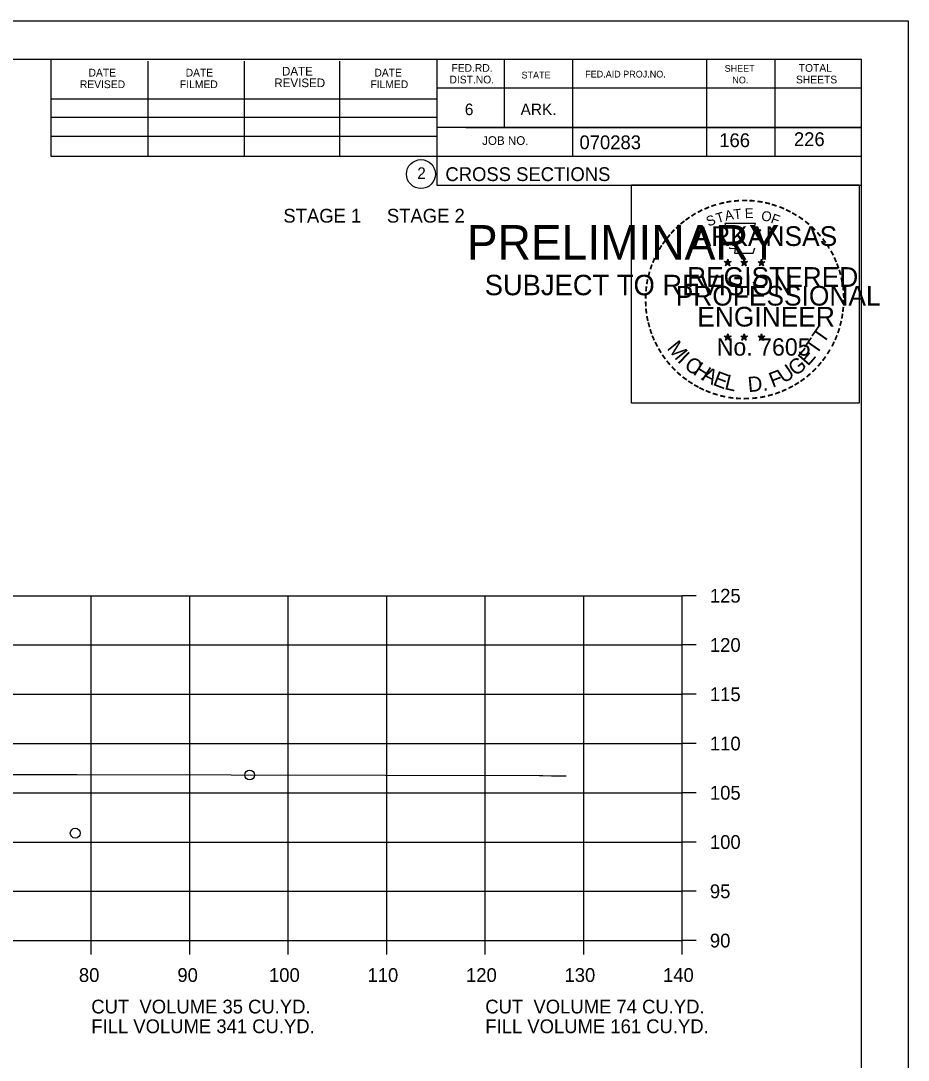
# Model space of a CAD drawing. Extents: x 1175611 to 1176402, y -433344 to -416213.
# Drawn here: x 1175853.8 to 1175943.9, y -429182.3 to -429076.8 of the extents above; entities that cross this region are included whole.
import ezdxf

# ---------------------------------------------------------------- set-up
doc = ezdxf.new("R2010")
doc.units = 0
for name, color, linetype in [('Default', 7, 'Continuous'), ('R_Axis', 7, 'Continuous'), ('R_Axis Annot', 7, 'Continuous'), ('R_Border', 7, 'Continuous'), ('R_Border Notes', 7, 'Continuous'), ('R_Border PE', 7, 'Continuous'), ('R_Border Prem', 7, 'Continuous'), ('R_Exist Surface', 7, 'Continuous'), ('R_Grid', 7, 'Continuous'), ('R_No Plot', 7, 'Continuous')]:
    doc.layers.add(name, color=color, linetype=linetype)

msp = doc.modelspace()

# ---------------------------------------------------------------- linework, layer by layer
at = {"layer": 'R_Axis'}
for p, q in [((1175920.97, -429170.13), (1175920.97, -429135.13)), ((1175922.37, -429135.13), (1175920.97, -429135.13)), ((1175922.37, -429140.13), (1175920.97, -429140.13)), ((1175922.37, -429145.13), (1175920.97, -429145.13)), ((1175922.37, -429150.13), (1175920.97, -429150.13)), ((1175922.37, -429155.13), (1175920.97, -429155.13)), ((1175922.37, -429160.13), (1175920.97, -429160.13)), ((1175922.37, -429165.13), (1175920.97, -429165.13)), ((1175640.97, -429170.13), (1175920.97, -429170.13)), ((1175860.97, -429171.53), (1175860.97, -429170.13)), ((1175870.97, -429171.53), (1175870.97, -429170.13)), ((1175880.97, -429171.53), (1175880.97, -429170.13)), ((1175890.97, -429171.53), (1175890.97, -429170.13)), ((1175900.97, -429171.53), (1175900.97, -429170.13)), ((1175910.97, -429171.53), (1175910.97, -429170.13)), ((1175920.97, -429171.53), (1175920.97, -429170.13)), ((1175922.37, -429170.13), (1175920.97, -429170.13))]:
    msp.add_line(p, q, dxfattribs=at)
at = {"layer": 'R_Border'}
for p, q in [((1175622.97, -429080.67), (1175939.15, -429080.67)), ((1175856.89, -429090.55), (1175856.89, -429080.67)), ((1175896.05, -429080.67), (1175896.05, -429093.47)), ((1175902.89, -429080.67), (1175902.89, -429087.61)), ((1175909.83, -429080.67), (1175909.83, -429090.55)), ((1175923.41, -429080.67), (1175923.41, -429090.55)), ((1175930.35, -429080.67), (1175930.35, -429090.55)), ((1175939.15, -429286.13), (1175939.15, -429080.67)), ((1175866.75, -429090.55), (1175866.75, -429080.87)), ((1175876.51, -429090.55), (1175876.51, -429080.87)), ((1175886.19, -429090.55), (1175886.19, -429080.87)), ((1175939.15, -429083.61), (1175896.05, -429083.61)), ((1175939.15, -429083.59), (1175939.15, -429083.59)), ((1175856.89, -429084.69), (1175896.05, -429084.69)), ((1175856.89, -429086.55), (1175896.05, -429086.55)), ((1175939.15, -429087.61), (1175896.05, -429087.61)), ((1175899.01, -429087.61), (1175939.15, -429087.61)), ((1175856.89, -429090.55), (1175856.89, -429088.49)), ((1175856.89, -429088.49), (1175896.05, -429088.49)), ((1175939.15, -429090.55), (1175856.89, -429090.55)), ((1175896.05, -429093.47), (1175939.15, -429093.47))]:
    msp.add_line(p, q, dxfattribs=at)
msp.add_circle((1175894.44, -429092.33), 1.47, dxfattribs=at)
at = {"layer": 'R_Border PE'}
for p, q in [((1175925.23, -429101.22), (1175925.58, -429101.33)), ((1175925.23, -429101.22), (1175925.49, -429101.27)), ((1175925.23, -429101.22), (1175925.47, -429101.34)), ((1175925.37, -429101.63), (1175925.58, -429101.33)), ((1175925.37, -429101.63), (1175925.49, -429101.39)), ((1175925.37, -429101.63), (1175925.58, -429101.41)), ((1175925.58, -429100.97), (1175925.54, -429101.22)), ((1175925.58, -429101.33), (1175925.58, -429100.97)), ((1175925.58, -429100.97), (1175925.63, -429101.22)), ((1175925.93, -429101.22), (1175925.58, -429101.33)), ((1175925.8, -429101.63), (1175925.58, -429101.33)), ((1175925.8, -429101.63), (1175925.58, -429101.42)), ((1175925.93, -429101.22), (1175925.64, -429101.27)), ((1175925.8, -429101.63), (1175925.66, -429101.34)), ((1175925.93, -429101.22), (1175925.73, -429101.32)), ((1175926.9, -429101.22), (1175927.25, -429101.33)), ((1175926.9, -429101.22), (1175927.16, -429101.27)), ((1175926.9, -429101.22), (1175927.14, -429101.34)), ((1175927.04, -429101.63), (1175927.25, -429101.33)), ((1175927.04, -429101.63), (1175927.16, -429101.39)), ((1175927.04, -429101.63), (1175927.25, -429101.41)), ((1175927.25, -429100.97), (1175927.21, -429101.22)), ((1175927.25, -429101.33), (1175927.25, -429100.97)), ((1175927.25, -429100.97), (1175927.3, -429101.22)), ((1175927.6, -429101.22), (1175927.25, -429101.33)), ((1175927.47, -429101.63), (1175927.25, -429101.33)), ((1175927.47, -429101.63), (1175927.25, -429101.42)), ((1175927.6, -429101.22), (1175927.31, -429101.27)), ((1175927.47, -429101.63), (1175927.33, -429101.34)), ((1175927.6, -429101.22), (1175927.4, -429101.32)), ((1175928.67, -429101.23), (1175929.02, -429101.34)), ((1175928.67, -429101.23), (1175928.92, -429101.28)), ((1175928.67, -429101.23), (1175928.91, -429101.36)), ((1175928.8, -429101.64), (1175929.02, -429101.34)), ((1175928.8, -429101.64), (1175928.93, -429101.4)), ((1175928.8, -429101.64), (1175929.02, -429101.42)), ((1175929.02, -429100.98), (1175928.98, -429101.23)), ((1175929.02, -429101.34), (1175929.02, -429100.98)), ((1175929.02, -429100.98), (1175929.07, -429101.23)), ((1175929.36, -429101.23), (1175929.02, -429101.34)), ((1175929.23, -429101.64), (1175929.02, -429101.34)), ((1175929.23, -429101.64), (1175929.02, -429101.43)), ((1175929.36, -429101.23), (1175929.08, -429101.28)), ((1175929.23, -429101.64), (1175929.09, -429101.35)), ((1175929.36, -429101.23), (1175929.16, -429101.34)), ((1175925.23, -429108.79), (1175925.58, -429108.91)), ((1175925.23, -429108.79), (1175925.48, -429108.84)), ((1175925.23, -429108.79), (1175925.47, -429108.92)), ((1175925.36, -429109.2), (1175925.58, -429108.91)), ((1175925.36, -429109.2), (1175925.49, -429108.96)), ((1175925.36, -429109.2), (1175925.58, -429108.99)), ((1175925.58, -429108.54), (1175925.54, -429108.79)), ((1175925.58, -429108.91), (1175925.58, -429108.54)), ((1175925.58, -429108.54), (1175925.63, -429108.79)), ((1175925.93, -429108.79), (1175925.58, -429108.91)), ((1175925.79, -429109.2), (1175925.58, -429108.91)), ((1175925.79, -429109.2), (1175925.58, -429108.99)), ((1175925.93, -429108.79), (1175925.64, -429108.84)), ((1175925.79, -429109.2), (1175925.66, -429108.91)), ((1175925.93, -429108.79), (1175925.72, -429108.9)), ((1175926.9, -429108.79), (1175927.25, -429108.91)), ((1175926.9, -429108.79), (1175927.15, -429108.84)), ((1175926.9, -429108.79), (1175927.14, -429108.92)), ((1175927.03, -429109.2), (1175927.25, -429108.91)), ((1175927.03, -429109.2), (1175927.16, -429108.96)), ((1175927.03, -429109.2), (1175927.25, -429108.99)), ((1175927.25, -429108.54), (1175927.21, -429108.79)), ((1175927.25, -429108.91), (1175927.25, -429108.54)), ((1175927.25, -429108.54), (1175927.3, -429108.79)), ((1175927.6, -429108.79), (1175927.25, -429108.91)), ((1175927.46, -429109.2), (1175927.25, -429108.91)), ((1175927.46, -429109.2), (1175927.25, -429108.99)), ((1175927.6, -429108.79), (1175927.31, -429108.84)), ((1175927.46, -429109.2), (1175927.32, -429108.91)), ((1175927.6, -429108.79), (1175927.39, -429108.9)), ((1175928.67, -429108.8), (1175929.02, -429108.92)), ((1175928.67, -429108.8), (1175928.92, -429108.85)), ((1175928.67, -429108.8), (1175928.9, -429108.93)), ((1175928.8, -429109.21), (1175929.02, -429108.92)), ((1175928.8, -429109.21), (1175928.93, -429108.97)), ((1175928.8, -429109.21), (1175929.01, -429109)), ((1175929.02, -429108.55), (1175928.97, -429108.8)), ((1175929.23, -429109.21), (1175929.01, -429109)), ((1175929.02, -429108.92), (1175929.02, -429108.55)), ((1175929.02, -429108.55), (1175929.06, -429108.8)), ((1175929.36, -429108.8), (1175929.02, -429108.92)), ((1175929.23, -429109.21), (1175929.02, -429108.92)), ((1175929.36, -429108.8), (1175929.08, -429108.85)), ((1175929.23, -429109.21), (1175929.09, -429108.92)), ((1175929.36, -429108.8), (1175929.16, -429108.91))]:
    msp.add_line(p, q, dxfattribs=at)
for points in [[(1175925.28, -429097.34), (1175925.54, -429098.17)], [(1175928.79, -429098.27), (1175928.93, -429097.98), (1175928.24, -429098.01), (1175928.39, -429097.34), (1175925.28, -429097.34)], [(1175925.77, -429099.77), (1175925.77, -429099.85), (1175926.33, -429099.87), (1175926.28, -429100.35), (1175928.15, -429100.35), (1175928.35, -429099.81)], [(1175925.58, -429100.97), (1175925.8, -429101.63), (1175925.23, -429101.22), (1175925.93, -429101.22), (1175925.37, -429101.63), (1175925.58, -429100.97)], [(1175927.25, -429100.97), (1175927.47, -429101.63), (1175926.9, -429101.22), (1175927.6, -429101.22), (1175927.04, -429101.63), (1175927.25, -429100.97)], [(1175929.02, -429100.98), (1175929.23, -429101.64), (1175928.67, -429101.23), (1175929.36, -429101.23), (1175928.8, -429101.64), (1175929.02, -429100.98)], [(1175925.58, -429108.54), (1175925.79, -429109.2), (1175925.23, -429108.79), (1175925.93, -429108.79), (1175925.36, -429109.2), (1175925.58, -429108.54)], [(1175927.25, -429108.54), (1175927.46, -429109.2), (1175926.9, -429108.79), (1175927.6, -429108.79), (1175927.03, -429109.2), (1175927.25, -429108.54)], [(1175929.02, -429108.55), (1175929.23, -429109.21), (1175928.67, -429108.8), (1175929.36, -429108.8), (1175928.8, -429109.21), (1175929.02, -429108.55)]]:
    msp.add_lwpolyline(points, dxfattribs=at)
for centre, radius in [((1175925.58, -429101.33), 0.172), ((1175925.58, -429101.33), 0.145), ((1175925.58, -429101.33), 0.116), ((1175925.58, -429101.33), 0.0991), ((1175925.58, -429101.33), 0.0747), ((1175925.58, -429101.33), 0.0495), ((1175925.58, -429101.33), 0.0296), ((1175927.25, -429101.33), 0.172), ((1175927.25, -429101.33), 0.145), ((1175927.25, -429101.33), 0.116), ((1175927.25, -429101.33), 0.0991), ((1175927.25, -429101.33), 0.0747), ((1175927.25, -429101.33), 0.0495), ((1175927.25, -429101.33), 0.0296), ((1175929.02, -429101.35), 0.172), ((1175929.02, -429101.35), 0.145), ((1175929.02, -429101.35), 0.116), ((1175929.02, -429101.35), 0.0991), ((1175929.02, -429101.35), 0.0747), ((1175929.02, -429101.35), 0.0495), ((1175929.02, -429101.35), 0.0296), ((1175925.58, -429108.91), 0.172), ((1175925.58, -429108.91), 0.145), ((1175925.58, -429108.91), 0.116), ((1175925.58, -429108.91), 0.0991), ((1175925.58, -429108.91), 0.0747), ((1175925.58, -429108.91), 0.0495), ((1175925.58, -429108.91), 0.0296), ((1175927.25, -429108.91), 0.172), ((1175927.25, -429108.91), 0.145), ((1175927.25, -429108.91), 0.116), ((1175927.25, -429108.91), 0.0991), ((1175927.25, -429108.91), 0.0747), ((1175927.25, -429108.91), 0.0495), ((1175927.25, -429108.91), 0.0296), ((1175929.01, -429108.92), 0.172), ((1175929.01, -429108.92), 0.145), ((1175929.01, -429108.92), 0.116), ((1175929.01, -429108.92), 0.0991), ((1175929.01, -429108.92), 0.0747), ((1175929.01, -429108.92), 0.0495), ((1175929.01, -429108.92), 0.0296)]:
    msp.add_circle(centre, radius, dxfattribs=at)
at = {"layer": 'R_Exist Surface'}
msp.add_lwpolyline([(1175852.41, -429153.27), (1175859.52, -429153.29), (1175906.46, -429153.39), (1175906.81, -429153.39), (1175907.7, -429153.4), (1175909.19, -429153.41)], dxfattribs=at)
at = {"layer": 'R_Grid'}
for p, q in [((1175640.97, -429135.13), (1175920.97, -429135.13)), ((1175860.97, -429170.13), (1175860.97, -429135.13)), ((1175870.97, -429170.13), (1175870.97, -429135.13)), ((1175880.97, -429170.13), (1175880.97, -429135.13)), ((1175890.97, -429170.13), (1175890.97, -429135.13)), ((1175900.97, -429170.13), (1175900.97, -429135.13)), ((1175910.97, -429170.13), (1175910.97, -429135.13)), ((1175920.97, -429170.13), (1175920.97, -429135.13)), ((1175640.97, -429140.13), (1175920.97, -429140.13)), ((1175640.97, -429145.13), (1175920.97, -429145.13)), ((1175640.97, -429150.13), (1175920.97, -429150.13)), ((1175640.97, -429155.13), (1175920.97, -429155.13)), ((1175640.97, -429160.13), (1175920.97, -429160.13)), ((1175640.97, -429165.13), (1175920.97, -429165.13)), ((1175640.97, -429170.13), (1175920.97, -429170.13))]:
    msp.add_line(p, q, dxfattribs=at)
at = {"layer": 'R_No Plot'}
msp.add_line((1175610.57, -429076.77), (1175943.91, -429076.77), dxfattribs=at)
for points in [[(1175610.57, -429076.77), (1175943.91, -429076.77), (1175943.91, -429290.11), (1175610.57, -429290.11)], [(1175915.82, -429093.44), (1175938.92, -429093.44), (1175938.92, -429115.59), (1175915.82, -429115.59)]]:
    msp.add_lwpolyline(points, close=True, dxfattribs=at)
for centre in [(1175877.05, -429153.33), (1175859.34, -429159.23)]:
    msp.add_circle(centre, 0.5, dxfattribs=at)

# ---------------------------------------------------------------- texts
at = {"layer": 'Default'}
for s, p in [('STAGE 1     STAGE 2', (1175880.47, -429097.26)), ('CUT  VOLUME 35 CU.YD.', (1175860.97, -429177.53)), ('CUT  VOLUME 74 CU.YD.', (1175900.97, -429177.53)), ('FILL VOLUME 341 CU.YD.', (1175860.97, -429179.53)), ('FILL VOLUME 161 CU.YD.', (1175900.97, -429179.53))]:
    msp.add_text(s, height=1.4, dxfattribs=at).set_placement(p)
at = {"layer": 'R_Axis Annot'}
for s, p in [('125', (1175923.77, -429135.83)), ('120', (1175923.77, -429140.83)), ('115', (1175923.77, -429145.83)), ('110', (1175923.77, -429150.83)), ('105', (1175923.77, -429155.83)), ('100', (1175923.77, -429160.83)), ('95', (1175923.77, -429165.83)), ('90', (1175923.77, -429170.83)), ('80', (1175859.71, -429174.33)), ('90', (1175869.71, -429174.33)), ('100', (1175879.01, -429174.33)), ('110', (1175889.01, -429174.33)), ('120', (1175899.01, -429174.33)), ('130', (1175909.01, -429174.33)), ('140', (1175919.01, -429174.33))]:
    msp.add_text(s, height=1.4, dxfattribs=at).set_placement(p)
at = {"layer": 'R_Border'}
for s, height, p in [('DATE', 0.782, (1175860.69, -429082.43)), ('DATE', 0.782, (1175870.55, -429082.43)), ('DATE', 0.879, (1175880.33, -429082.33)), ('DATE', 0.782, (1175889.71, -429082.43)), ('FED.RD.', 0.782, (1175897.53, -429081.95)), ('SHEET', 0.684, (1175925.27, -429081.95)), ('TOTAL', 0.782, (1175932.79, -429081.95)), ('REVISED', 0.782, (1175859.81, -429083.61)), ('FILMED', 0.782, (1175869.97, -429083.61)), ('REVISED', 0.879, (1175879.55, -429083.51)), ('FILMED', 0.782, (1175889.31, -429083.61)), ('DIST.NO.', 0.782, (1175897.33, -429083.13)), ('STATE', 0.684, (1175904.65, -429082.63)), ('FED.AID PROJ.NO.', 0.684, (1175911.11, -429082.53)), ('NO.', 0.684, (1175926.05, -429083.13)), ('SHEETS', 0.782, (1175932.51, -429083.13)), ('6', 1.17, (1175898.89, -429086.35)), ('ARK.', 1.172, (1175904.55, -429086.35)), ('JOB NO.', 0.879, (1175900.65, -429089.37)), ('070283', 1.4, (1175910.53, -429089.81)), ('2', 1.17, (1175894.06, -429092.82)), ('CROSS SECTIONS', 1.4, (1175896.92, -429093.04))]:
    msp.add_text(s, height=height, rotation=360, dxfattribs=at).set_placement(p)
at = {"layer": 'R_Border Notes'}
for s, p in [('226', (1175932.3, -429089.49)), ('166', (1175924.72, -429089.6))]:
    msp.add_text(s, height=1.4, dxfattribs=at).set_placement(p)
at = {"layer": 'R_Border PE'}
for s, height, rotation, p in [('-', 1.6, 19.1761, (1175924.02, -429096.22)), ('-', 1.6, 13.6301, (1175924.77, -429095.98)), ('-', 1.6, 10.2193, (1175925.45, -429095.81)), ('-', 1.6, 5.8968, (1175926.18, -429095.7)), ('-', 1.6, 0.1862, (1175926.95, -429095.63)), ('-', 1.6, 357.743, (1175927.67, -429095.64)), ('-', 1.6, 352.1617, (1175928.42, -429095.7)), ('-', 1.6, 347.2049, (1175929.14, -429095.81)), ('-', 1.6, 342.3362, (1175929.77, -429095.97)), ('-', 1.6, 34.0636, (1175922.16, -429097.17)), ('-', 1.6, 28.7918, (1175922.76, -429096.8)), ('-', 1.6, 24.3072, (1175923.39, -429096.49)), ('S', 1, 21.594, (1175923.63, -429097.67)), ('T', 1, 16.4036, (1175924.54, -429097.33)), ('A', 1, 11.2132, (1175925.37, -429097.08)), ('T', 1, 6.0228, (1175926.22, -429096.92)), ('E', 1, 0.8323, (1175927.32, -429096.81)), ('O', 1, 350.4515, (1175928.93, -429097.02)), ('F', 1, 340.0707, (1175929.88, -429097.25)), ('-', 1.6, 337.8551, (1175930.51, -429096.19)), ('-', 1.6, 334.1211, (1175931.14, -429096.46)), ('-', 1.6, 329.6409, (1175931.72, -429096.75)), ('-', 1.6, 42.9622, (1175920.67, -429098.36)), ('-', 1.6, 38.9507, (1175921.1, -429097.95)), ('-', 1.6, 36.2317, (1175921.58, -429097.57)), ('ARKANSAS', 2, 360, (1175922.13, -429099.63)), ('-', 1.6, 325.8627, (1175932.36, -429097.11)), ('-', 1.6, 320.5297, (1175932.97, -429097.53)), ('-', 1.6, 315.5786, (1175933.57, -429098.02)), ('-', 1.6, 50.6142, (1175919.82, -429099.33)), ('-', 1.6, 48.423, (1175920.22, -429098.84)), ('-', 1.6, 309.8797, (1175934.14, -429098.57)), ('-', 1.6, 58.0706, (1175919.08, -429100.42)), ('-', 1.6, 54.2325, (1175919.41, -429099.89)), ('-', 1.6, 306.6522, (1175934.66, -429099.17)), ('-', 1.4, 303.6753, (1175935.15, -429099.74)), ('-', 1.6, 62.8713, (1175918.77, -429101.03)), ('-', 1.6, 299.6684, (1175935.47, -429100.35)), ('-', 1.6, 294.6628, (1175935.79, -429100.96)), ('-', 1.6, 72.3945, (1175918.29, -429102.28)), ('-', 1.6, 67.7743, (1175918.51, -429101.65)), ('REGISTERED', 2, 360, (1175921.45, -429103.78)), ('DWB', 0.01, 360, (1175925.57, -429101.34)), ('DWB', 0.01, 360, (1175927.24, -429101.34)), ('DWB', 0.01, 360, (1175929, -429101.35)), ('-', 1.6, 290.5728, (1175936.05, -429101.54)), ('-', 1.6, 75.461, (1175918.09, -429102.99)), ('-', 1.6, 285.1233, (1175936.28, -429102.12)), ('-', 1.6, 280.5493, (1175936.48, -429102.86)), ('-', 1.6, 85.1863, (1175917.89, -429104.39)), ('-', 1.6, 81.2013, (1175917.96, -429103.7)), ('PROFESSIONAL', 2, 360, (1175920.3, -429105.68)), ('-', 1.6, 276.5962, (1175936.65, -429103.63)), ('-', 1.6, 89.0622, (1175917.86, -429105.09)), ('-', 1.6, 274.3301, (1175936.71, -429104.35)), ('-', 1.6, 94.1959, (1175917.9, -429105.82)), ('-', 1.6, 98.9479, (1175917.97, -429106.49)), ('ENGINEER', 2, 360, (1175922.49, -429107.81)), ('-', 1.6, 263.5172, (1175936.72, -429105.65)), ('-', 1.6, 269.9407, (1175936.74, -429104.98)), ('-', 1.6, 101.7149, (1175918.1, -429107.22)), ('-', 1.6, 260.9953, (1175936.65, -429106.3)), ('-', 1.6, 105.4578, (1175918.27, -429107.81)), ('-', 1.6, 109.0874, (1175918.48, -429108.45)), ('T', 1.54, 55.055, (1175935.3, -429109.64)), ('-', 1.6, 252.8681, (1175936.36, -429107.7)), ('-', 1.6, 255.7626, (1175936.54, -429106.98)), ('-', 1.6, 114.0643, (1175918.73, -429109.04)), ('M', 1.54, 308.9175, (1175919.35, -429110.02)), ('No. 7605', 1.757, 360, (1175924.46, -429110.76)), ('DWB', 0.01, 360, (1175925.56, -429108.91)), ('DWB', 0.01, 360, (1175927.23, -429108.91)), ('DWB', 0.01, 360, (1175929, -429108.92)), ('T', 1.54, 55.055, (1175934.57, -429110.76)), ('-', 1.6, 247.8887, (1175936.14, -429108.37)), ('-', 1.6, 115.7289, (1175919.04, -429109.66)), ('-', 1.6, 120.4471, (1175919.4, -429110.25)), ('E', 1.54, 48.7313, (1175933.72, -429111.89)), ('-', 1.6, 239.0712, (1175935.48, -429109.75)), ('-', 1.6, 244.6197, (1175935.87, -429109)), ('-', 1.6, 125.8934, (1175919.8, -429110.81)), ('-', 1.6, 130.7181, (1175920.26, -429111.36)), ('I', 1.54, 316.4636, (1175920.39, -429111.34)), ('C', 1.54, 324.0197, (1175921.06, -429111.96)), ('G', 1.54, 38.2173, (1175932.47, -429112.91)), ('-', 1.6, 233.8452, (1175935.08, -429110.41)), ('-', 1.6, 134.2238, (1175920.78, -429111.9)), ('-', 1.6, 138.9338, (1175921.3, -429112.37)), ('H', 1.54, 327.5342, (1175921.97, -429112.61)), ('A', 1.54, 332.5513, (1175922.83, -429113.15)), ('E', 1.54, 339.2068, (1175923.99, -429113.71)), ('F', 1.54, 20.8202, (1175930.13, -429114.04)), ('U', 1.54, 34.4052, (1175931.27, -429113.64)), ('-', 1.6, 225.7653, (1175934.17, -429111.54)), ('-', 1.6, 231.2538, (1175934.65, -429110.97)), ('-', 1.6, 144.6463, (1175921.86, -429112.77)), ('-', 1.6, 148.0898, (1175922.42, -429113.14)), ('L', 1.54, 346.2929, (1175925.18, -429114.14)), ('D.', 1.54, 5.2602, (1175927.68, -429114.47)), ('-', 1.6, 212.2491, (1175932.56, -429112.9)), ('-', 1.6, 215.7363, (1175933.1, -429112.52)), ('-', 1.6, 221.0851, (1175933.65, -429112.05)), ('-', 1.6, 151.5704, (1175923, -429113.47)), ('-', 1.6, 154.6002, (1175923.52, -429113.72)), ('-', 1.6, 158.5612, (1175924.15, -429113.97)), ('-', 1.6, 162.7983, (1175924.83, -429114.18)), ('-', 1.6, 200.7184, (1175930.76, -429113.84)), ('-', 1.6, 204.2516, (1175931.38, -429113.57)), ('-', 1.6, 207.3568, (1175932.01, -429113.25)), ('-', 1.6, 167.5555, (1175925.55, -429114.35)), ('-', 1.6, 173.1155, (1175926.32, -429114.46)), ('-', 1.6, 176.5183, (1175927.07, -429114.51)), ('-', 1.6, 181.5918, (1175927.81, -429114.49)), ('-', 1.6, 185.8167, (1175928.62, -429114.42)), ('-', 1.6, 191.2858, (1175929.36, -429114.28)), ('-', 1.6, 195.4743, (1175930.09, -429114.08))]:
    msp.add_text(s, height=height, rotation=rotation, dxfattribs=at).set_placement(p)
at = {"layer": 'R_Border Prem'}
for s, height, p in [('PRELIMINARY', 3.5, (1175899.1, -429101.01)), ('DWB', 0.01, (1175899.85, -429099.16)), ('SUBJECT TO REVISION', 2.0751, (1175900.91, -429104.63))]:
    msp.add_text(s, height=height, rotation=360, dxfattribs=at).set_placement(p)

doc.saveas('drawing.dxf')
